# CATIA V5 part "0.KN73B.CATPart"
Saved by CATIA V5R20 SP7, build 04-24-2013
Part number: 0.KN73B
Material "Nessuno"
Bounding box of the stored display mesh (mm): x -30.572 to 149.213, y -143.683 to 0, z -56.919 to 41.584
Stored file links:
  C:\Users\designer2\Desktop\Ottobre 2022\25-10-2022\04\Yori Evo 48V\0.KN73B.CATPart
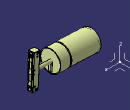
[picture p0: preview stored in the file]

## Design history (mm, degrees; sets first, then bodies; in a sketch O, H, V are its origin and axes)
AxisSystem1: origin (0, 0, 0), X (1, 0, 0), Y (0, 1, 0), Z (0, 0, 1)
Set1
  DatumSurface1
Body1 (main body), material "Nessuno"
